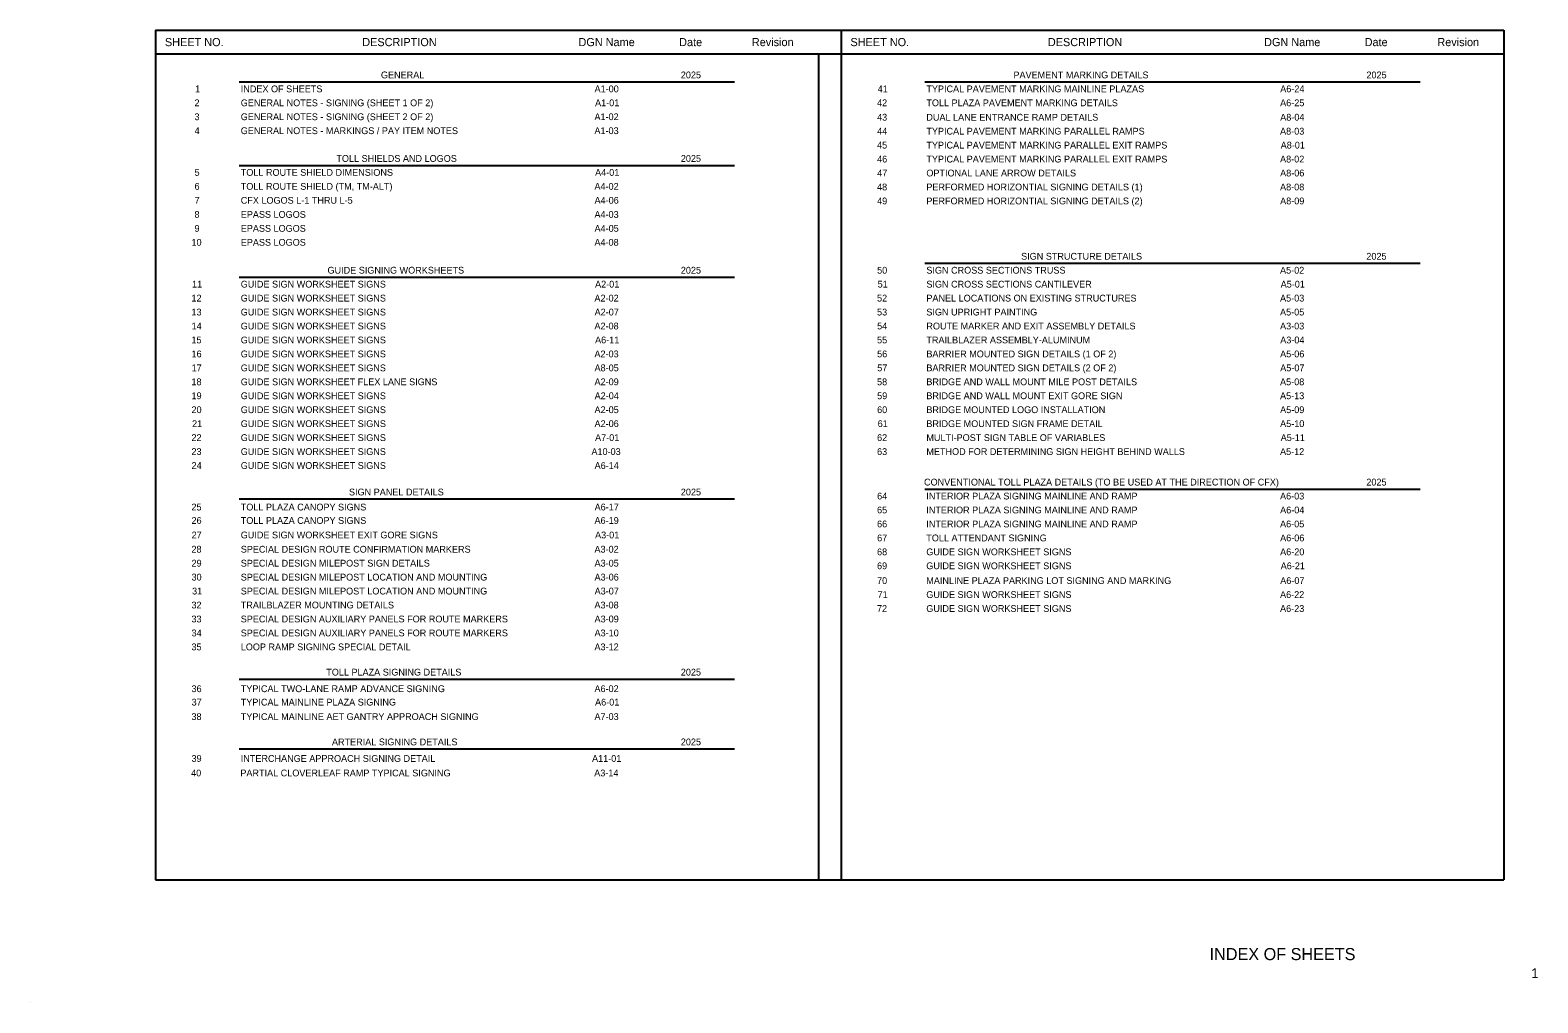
# Model space of a CAD drawing. Extents: x 2479979.8 to 2479999.3, y 3680687.9 to 3680700.4.
import ezdxf

# ---------------------------------------------------------------- set-up
doc = ezdxf.new("R2010")
doc.units = 0
for name, color, linetype in [('AdhocPoint_dp', 7, 'Continuous'), ('SumBoxLines_dp', 7, 'Continuous'), ('TextLabel', 7, 'Continuous'), ('TextMisc', 7, 'Continuous'), ('TextShtNo', 7, 'Continuous')]:
    doc.layers.add(name, color=color, linetype=linetype)

msp = doc.modelspace()

# ---------------------------------------------------------------- linework, layer by layer
at = {"layer": 'AdhocPoint_dp'}
msp.add_line((2479979.842, 3680687.871), (2479979.842, 3680687.871), dxfattribs=at)
at = {"layer": 'SumBoxLines_dp'}
for p, q in [((2479981.458, 3680700.422), (2479998.85, 3680700.422)), ((2479981.458, 3680700.422), (2479981.458, 3680689.458)), ((2479990.3, 3680700.422), (2479990.3, 3680690.034)), ((2479998.85, 3680700.422), (2479998.85, 3680689.458)), ((2479981.458, 3680700.114), (2479998.85, 3680700.114)), ((2479981.458, 3680700.114), (2479998.85, 3680700.114)), ((2479990.008, 3680700.114), (2479990.008, 3680691.294)), ((2479990.008, 3680700.025), (2479990.008, 3680689.458)), ((2479990.3, 3680700.025), (2479990.3, 3680689.458)), ((2479982.538, 3680699.754), (2479988.928, 3680699.754)), ((2479982.538, 3680699.754), (2479988.928, 3680699.754)), ((2479991.381, 3680699.754), (2479997.771, 3680699.754)), ((2479991.381, 3680699.754), (2479997.771, 3680699.754)), ((2479982.538, 3680698.675), (2479988.928, 3680698.675)), ((2479982.538, 3680698.675), (2479988.928, 3680698.675)), ((2479991.381, 3680697.414), (2479997.771, 3680697.414)), ((2479991.381, 3680697.414), (2479997.771, 3680697.414)), ((2479982.538, 3680697.234), (2479988.928, 3680697.234)), ((2479982.538, 3680697.234), (2479988.928, 3680697.234)), ((2479991.38, 3680694.5), (2479997.77, 3680694.5)), ((2479991.38, 3680694.5), (2479997.77, 3680694.5)), ((2479982.538, 3680694.372), (2479988.928, 3680694.372)), ((2479982.538, 3680692.047), (2479988.928, 3680692.047)), ((2479982.538, 3680692.047), (2479988.928, 3680692.047)), ((2479982.538, 3680691.147), (2479988.928, 3680691.147)), ((2479982.538, 3680691.147), (2479988.928, 3680691.147)), ((2479981.458, 3680689.458), (2479998.85, 3680689.458))]:
    msp.add_line(p, q, dxfattribs=at)

# ---------------------------------------------------------------- texts
at = {"layer": 'TextLabel'}
for s, height, p in [('SHEET NO.', 0.105, (2479981.58, 3680700.215)), ('DESCRIPTION', 0.105, (2479984.125, 3680700.215)), ('DGN Name', 0.105, (2479986.914, 3680700.215)), ('Date', 0.105, (2479988.212, 3680700.215)), ('Revision', 0.105, (2479989.15, 3680700.215)), ('SHEET NO.', 0.105, (2479990.422, 3680700.215)), ('DESCRIPTION', 0.105, (2479992.968, 3680700.215)), ('DGN Name', 0.105, (2479995.757, 3680700.215)), ('Date', 0.105, (2479997.054, 3680700.215)), ('Revision', 0.105, (2479997.992, 3680700.215)), ('GENERAL', 0.0875, (2479984.366, 3680699.8)), ('2025', 0.0875, (2479988.234, 3680699.8)), ('PAVEMENT MARKING DETAILS', 0.0875, (2479992.524, 3680699.8)), ('2025', 0.0875, (2479997.077, 3680699.8)), ('2', 0.0875, (2479981.961, 3680699.44)), ('1', 0.0875, (2479981.969, 3680699.62)), ('GENERAL NOTES - SIGNING (SHEET 1 OF 2)', 0.0875, (2479982.558, 3680699.44)), ('INDEX OF SHEETS', 0.0875, (2479982.558, 3680699.62)), ('A1-00', 0.0875, (2479987.121, 3680699.62)), ('A1-01', 0.0875, (2479987.128, 3680699.44)), ('42', 0.0875, (2479990.765, 3680699.44)), ('41', 0.0875, (2479990.773, 3680699.62)), ('TYPICAL PAVEMENT MARKING MAINLINE PLAZAS', 0.0875, (2479991.401, 3680699.62)), ('TOLL PLAZA PAVEMENT MARKING DETAILS', 0.0875, (2479991.401, 3680699.44)), ('A6-25', 0.0875, (2479995.964, 3680699.44)), ('A6-24', 0.0875, (2479995.965, 3680699.62)), ('3', 0.0875, (2479981.961, 3680699.26)), ('GENERAL NOTES - SIGNING (SHEET 2 OF 2)', 0.0875, (2479982.558, 3680699.26)), ('A1-02', 0.0875, (2479987.12, 3680699.26)), ('43', 0.0875, (2479990.765, 3680699.254)), ('DUAL LANE ENTRANCE RAMP DETAILS', 0.0875, (2479991.401, 3680699.254)), ('A8-04', 0.0875, (2479995.965, 3680699.254)), ('4', 0.0875, (2479981.963, 3680699.08)), ('GENERAL NOTES - MARKINGS / PAY ITEM NOTES', 0.0875, (2479982.558, 3680699.08)), ('A1-03', 0.0875, (2479987.12, 3680699.08)), ('44', 0.0875, (2479990.766, 3680699.074)), ('TYPICAL PAVEMENT MARKING PARALLEL RAMPS', 0.0875, (2479991.401, 3680699.074)), ('A8-03', 0.0875, (2479995.963, 3680699.074)), ('45', 0.0875, (2479990.765, 3680698.894)), ('TYPICAL PAVEMENT MARKING PARALLEL EXIT RAMPS', 0.0875, (2479991.401, 3680698.894)), ('A8-01', 0.0875, (2479995.971, 3680698.894)), ('TOLL SHIELDS AND LOGOS', 0.0875, (2479983.791, 3680698.722)), ('2025', 0.0875, (2479988.234, 3680698.722)), ('46', 0.0875, (2479990.766, 3680698.714)), ('TYPICAL PAVEMENT MARKING PARALLEL EXIT RAMPS', 0.0875, (2479991.401, 3680698.714)), ('A8-02', 0.0875, (2479995.963, 3680698.714)), ('5', 0.0875, (2479981.962, 3680698.542)), ('TOLL ROUTE SHIELD DIMENSIONS', 0.0875, (2479982.558, 3680698.542)), ('A4-01', 0.0875, (2479987.128, 3680698.542)), ('47', 0.0875, (2479990.767, 3680698.534)), ('OPTIONAL LANE ARROW DETAILS', 0.0875, (2479991.401, 3680698.534)), ('A8-06', 0.0875, (2479995.964, 3680698.534)), ('6', 0.0875, (2479981.962, 3680698.362)), ('TOLL ROUTE SHIELD (TM, TM-ALT)', 0.0875, (2479982.558, 3680698.362)), ('A4-02', 0.0875, (2479987.12, 3680698.362)), ('48', 0.0875, (2479990.765, 3680698.354)), ('PERFORMED HORIZONTIAL SIGNING DETAILS (1)', 0.0875, (2479991.401, 3680698.354)), ('A8-08', 0.0875, (2479995.963, 3680698.354)), ('7', 0.0875, (2479981.963, 3680698.182)), ('CFX LOGOS L-1 THRU L-5', 0.0875, (2479982.558, 3680698.182)), ('A4-06', 0.0875, (2479987.121, 3680698.182)), ('49', 0.0875, (2479990.766, 3680698.174)), ('PERFORMED HORIZONTIAL SIGNING DETAILS (2)', 0.0875, (2479991.401, 3680698.174)), ('A8-09', 0.0875, (2479995.964, 3680698.174)), ('8', 0.0875, (2479981.961, 3680698)), ('EPASS LOGOS', 0.0875, (2479982.558, 3680698)), ('A4-03', 0.0875, (2479987.12, 3680698)), ('9', 0.0875, (2479981.962, 3680697.82)), ('EPASS LOGOS', 0.0875, (2479982.558, 3680697.82)), ('A4-05', 0.0875, (2479987.121, 3680697.82)), ('10', 0.0875, (2479981.923, 3680697.64)), ('EPASS LOGOS', 0.0875, (2479982.558, 3680697.64)), ('A4-08', 0.0875, (2479987.12, 3680697.64)), ('SIGN STRUCTURE DETAILS', 0.0875, (2479992.623, 3680697.46)), ('2025', 0.0875, (2479997.076, 3680697.46)), ('11', 0.0875, (2479981.93, 3680697.1)), ('GUIDE SIGN WORKSHEET SIGNS', 0.0875, (2479982.558, 3680697.1)), ('GUIDE SIGNING WORKSHEETS', 0.0875, (2479983.677, 3680697.28)), ('A2-01', 0.0875, (2479987.128, 3680697.1)), ('2025', 0.0875, (2479988.234, 3680697.28)), ('50', 0.0875, (2479990.766, 3680697.28)), ('51', 0.0875, (2479990.773, 3680697.1)), ('SIGN CROSS SECTIONS TRUSS', 0.0875, (2479991.401, 3680697.28)), ('SIGN CROSS SECTIONS CANTILEVER', 0.0875, (2479991.401, 3680697.1)), ('A5-02', 0.0875, (2479995.963, 3680697.28)), ('A5-01', 0.0875, (2479995.971, 3680697.1)), ('12', 0.0875, (2479981.922, 3680696.92)), ('GUIDE SIGN WORKSHEET SIGNS', 0.0875, (2479982.558, 3680696.92)), ('A2-02', 0.0875, (2479987.12, 3680696.92)), ('52', 0.0875, (2479990.765, 3680696.92)), ('PANEL LOCATIONS ON EXISTING STRUCTURES', 0.0875, (2479991.401, 3680696.92)), ('A5-03', 0.0875, (2479995.963, 3680696.92)), ('13', 0.0875, (2479981.922, 3680696.74)), ('GUIDE SIGN WORKSHEET SIGNS', 0.0875, (2479982.558, 3680696.74)), ('A2-07', 0.0875, (2479987.122, 3680696.74)), ('53', 0.0875, (2479990.765, 3680696.74)), ('SIGN UPRIGHT PAINTING', 0.0875, (2479991.401, 3680696.74)), ('A5-05', 0.0875, (2479995.963, 3680696.74)), ('14', 0.0875, (2479981.924, 3680696.56)), ('GUIDE SIGN WORKSHEET SIGNS', 0.0875, (2479982.558, 3680696.56)), ('A2-08', 0.0875, (2479987.12, 3680696.56)), ('54', 0.0875, (2479990.766, 3680696.56)), ('ROUTE MARKER AND EXIT ASSEMBLY DETAILS', 0.0875, (2479991.401, 3680696.56)), ('A3-03', 0.0875, (2479995.963, 3680696.56)), ('15', 0.0875, (2479981.922, 3680696.38)), ('GUIDE SIGN WORKSHEET SIGNS', 0.0875, (2479982.558, 3680696.38)), ('A6-11', 0.0875, (2479987.128, 3680696.38)), ('55', 0.0875, (2479990.765, 3680696.38)), ('TRAILBLAZER ASSEMBLY-ALUMINUM', 0.0875, (2479991.401, 3680696.38)), ('A3-04', 0.0875, (2479995.965, 3680696.38)), ('16', 0.0875, (2479981.923, 3680696.2)), ('GUIDE SIGN WORKSHEET SIGNS', 0.0875, (2479982.558, 3680696.2)), ('A2-03', 0.0875, (2479987.12, 3680696.2)), ('56', 0.0875, (2479990.766, 3680696.2)), ('BARRIER MOUNTED SIGN DETAILS (1 OF 2)', 0.0875, (2479991.401, 3680696.2)), ('A5-06', 0.0875, (2479995.964, 3680696.2)), ('17', 0.0875, (2479981.924, 3680696.02)), ('GUIDE SIGN WORKSHEET SIGNS', 0.0875, (2479982.558, 3680696.02)), ('A8-05', 0.0875, (2479987.121, 3680696.02)), ('57', 0.0875, (2479990.767, 3680696.02)), ('BARRIER MOUNTED SIGN DETAILS (2 OF 2)', 0.0875, (2479991.401, 3680696.02)), ('A5-07', 0.0875, (2479995.965, 3680696.02)), ('18', 0.0875, (2479981.922, 3680695.84)), ('GUIDE SIGN WORKSHEET FLEX LANE SIGNS', 0.0875, (2479982.558, 3680695.84)), ('A2-09', 0.0875, (2479987.121, 3680695.84)), ('58', 0.0875, (2479990.765, 3680695.84)), ('BRIDGE AND WALL MOUNT MILE POST DETAILS', 0.0875, (2479991.401, 3680695.84)), ('A5-08', 0.0875, (2479995.963, 3680695.84)), ('19', 0.0875, (2479981.923, 3680695.66)), ('GUIDE SIGN WORKSHEET SIGNS', 0.0875, (2479982.558, 3680695.66)), ('A2-04', 0.0875, (2479987.122, 3680695.66)), ('59', 0.0875, (2479990.766, 3680695.66)), ('BRIDGE AND WALL MOUNT EXIT GORE SIGN', 0.0875, (2479991.401, 3680695.66)), ('A5-13', 0.0875, (2479995.963, 3680695.66)), ('20', 0.0875, (2479981.923, 3680695.48)), ('GUIDE SIGN WORKSHEET SIGNS', 0.0875, (2479982.558, 3680695.48)), ('A2-05', 0.0875, (2479987.121, 3680695.48)), ('60', 0.0875, (2479990.766, 3680695.48)), ('BRIDGE MOUNTED LOGO INSTALLATION', 0.0875, (2479991.401, 3680695.48)), ('A5-09', 0.0875, (2479995.964, 3680695.48)), ('21', 0.0875, (2479981.93, 3680695.3)), ('GUIDE SIGN WORKSHEET SIGNS', 0.0875, (2479982.558, 3680695.3)), ('A2-06', 0.0875, (2479987.121, 3680695.3)), ('61', 0.0875, (2479990.773, 3680695.3)), ('BRIDGE MOUNTED SIGN FRAME DETAIL', 0.0875, (2479991.401, 3680695.3)), ('A5-10', 0.0875, (2479995.964, 3680695.3)), ('22', 0.0875, (2479981.922, 3680695.12)), ('GUIDE SIGN WORKSHEET SIGNS', 0.0875, (2479982.558, 3680695.12)), ('A7-01', 0.0875, (2479987.128, 3680695.12)), ('62', 0.0875, (2479990.765, 3680695.12)), ('MULTI-POST SIGN TABLE OF VARIABLES', 0.0875, (2479991.401, 3680695.12)), ('A5-11', 0.0875, (2479995.971, 3680695.12)), ('23', 0.0875, (2479981.922, 3680694.94)), ('GUIDE SIGN WORKSHEET SIGNS', 0.0875, (2479982.558, 3680694.94)), ('A10-03', 0.0875, (2479987.081, 3680694.94)), ('63', 0.0875, (2479990.765, 3680694.94)), ('METHOD FOR DETERMINING SIGN HEIGHT BEHIND WALLS', 0.0875, (2479991.401, 3680694.94)), ('A5-12', 0.0875, (2479995.963, 3680694.94)), ('24', 0.0875, (2479981.924, 3680694.76)), ('GUIDE SIGN WORKSHEET SIGNS', 0.0875, (2479982.558, 3680694.76)), ('A6-14', 0.0875, (2479987.122, 3680694.76)), ('SIGN PANEL DETAILS', 0.0875, (2479983.954, 3680694.418)), ('2025', 0.0875, (2479988.234, 3680694.418)), ('CONVENTIONAL TOLL PLAZA DETAILS (TO BE USED AT THE DIRECTION OF CFX)', 0.0875, (2479991.371, 3680694.546)), ('2025', 0.0875, (2479997.076, 3680694.546)), ('25', 0.0875, (2479981.922, 3680694.224)), ('TOLL PLAZA CANOPY SIGNS', 0.0875, (2479982.558, 3680694.224)), ('A6-17', 0.0875, (2479987.122, 3680694.224)), ('65', 0.0875, (2479990.765, 3680694.186)), ('64', 0.0875, (2479990.766, 3680694.366)), ('INTERIOR PLAZA SIGNING MAINLINE AND RAMP', 0.0875, (2479991.4, 3680694.366)), ('INTERIOR PLAZA SIGNING MAINLINE AND RAMP', 0.0875, (2479991.4, 3680694.186)), ('A6-03', 0.0875, (2479995.963, 3680694.366)), ('A6-04', 0.0875, (2479995.964, 3680694.186)), ('26', 0.0875, (2479981.923, 3680694.051)), ('TOLL PLAZA CANOPY SIGNS', 0.0875, (2479982.558, 3680694.051)), ('A6-19', 0.0875, (2479987.121, 3680694.051)), ('66', 0.0875, (2479990.765, 3680694.006)), ('INTERIOR PLAZA SIGNING MAINLINE AND RAMP', 0.0875, (2479991.4, 3680694.006)), ('A6-05', 0.0875, (2479995.963, 3680694.006)), ('27', 0.0875, (2479981.924, 3680693.864)), ('GUIDE SIGN WORKSHEET EXIT GORE SIGNS', 0.0875, (2479982.558, 3680693.864)), ('A3-01', 0.0875, (2479987.128, 3680693.864)), ('67', 0.0875, (2479990.766, 3680693.826)), ('TOLL ATTENDANT SIGNING', 0.0875, (2479991.4, 3680693.826)), ('A6-06', 0.0875, (2479995.964, 3680693.826)), ('28', 0.0875, (2479981.922, 3680693.68)), ('SPECIAL DESIGN ROUTE CONFIRMATION MARKERS', 0.0875, (2479982.558, 3680693.68)), ('A3-02', 0.0875, (2479987.12, 3680693.68)), ('68', 0.0875, (2479990.765, 3680693.646)), ('GUIDE SIGN WORKSHEET SIGNS ', 0.0875, (2479991.4, 3680693.646)), ('A6-20', 0.0875, (2479995.964, 3680693.646)), ('29', 0.0875, (2479981.923, 3680693.5)), ('SPECIAL DESIGN MILEPOST SIGN DETAILS', 0.0875, (2479982.558, 3680693.5)), ('A3-05', 0.0875, (2479987.121, 3680693.5)), ('69', 0.0875, (2479990.765, 3680693.466)), ('GUIDE SIGN WORKSHEET SIGNS ', 0.0875, (2479991.4, 3680693.466)), ('A6-21', 0.0875, (2479995.971, 3680693.466)), ('30', 0.0875, (2479981.923, 3680693.32)), ('SPECIAL DESIGN MILEPOST LOCATION AND MOUNTING', 0.0875, (2479982.558, 3680693.32)), ('A3-06', 0.0875, (2479987.121, 3680693.32)), ('70', 0.0875, (2479990.765, 3680693.275)), ('MAINLINE PLAZA PARKING LOT SIGNING AND MARKING', 0.0875, (2479991.4, 3680693.275)), ('A6-07', 0.0875, (2479995.965, 3680693.275)), ('31', 0.0875, (2479981.93, 3680693.14)), ('SPECIAL DESIGN MILEPOST LOCATION AND MOUNTING', 0.0875, (2479982.558, 3680693.14)), ('A3-07', 0.0875, (2479987.122, 3680693.14)), ('71', 0.0875, (2479990.772, 3680693.095)), ('GUIDE SIGN WORKSHEET SIGNS', 0.0875, (2479991.4, 3680693.095)), ('A6-22', 0.0875, (2479995.963, 3680693.095)), ('32', 0.0875, (2479981.922, 3680692.96)), ('TRAILBLAZER MOUNTING DETAILS', 0.0875, (2479982.558, 3680692.96)), ('A3-08', 0.0875, (2479987.12, 3680692.96)), ('72', 0.0875, (2479990.764, 3680692.915)), ('GUIDE SIGN WORKSHEET SIGNS', 0.0875, (2479991.4, 3680692.915)), ('A6-23', 0.0875, (2479995.963, 3680692.915)), ('33', 0.0875, (2479981.922, 3680692.78)), ('SPECIAL DESIGN AUXILIARY PANELS FOR ROUTE MARKERS', 0.0875, (2479982.558, 3680692.78)), ('A3-09', 0.0875, (2479987.121, 3680692.78)), ('34', 0.0875, (2479981.924, 3680692.6)), ('SPECIAL DESIGN AUXILIARY PANELS FOR ROUTE MARKERS', 0.0875, (2479982.558, 3680692.6)), ('A3-10', 0.0875, (2479987.121, 3680692.6)), ('35', 0.0875, (2479981.922, 3680692.42)), ('LOOP RAMP SIGNING SPECIAL DETAIL', 0.0875, (2479982.558, 3680692.42)), ('A3-12', 0.0875, (2479987.12, 3680692.42)), ('TOLL PLAZA SIGNING DETAILS', 0.0875, (2479983.661, 3680692.094)), ('2025', 0.0875, (2479988.234, 3680692.094)), ('36', 0.0875, (2479981.923, 3680691.88)), ('TYPICAL TWO-LANE RAMP ADVANCE SIGNING', 0.0875, (2479982.558, 3680691.88)), ('A6-02', 0.0875, (2479987.12, 3680691.88)), ('37', 0.0875, (2479981.924, 3680691.707)), ('TYPICAL MAINLINE PLAZA SIGNING', 0.0875, (2479982.558, 3680691.707)), ('A6-01', 0.0875, (2479987.128, 3680691.707)), ('38', 0.0875, (2479981.922, 3680691.52)), ('TYPICAL MAINLINE AET GANTRY APPROACH SIGNING', 0.0875, (2479982.558, 3680691.52)), ('A7-03', 0.0875, (2479987.12, 3680691.52)), ('ARTERIAL SIGNING DETAILS', 0.0875, (2479983.734, 3680691.194)), ('2025', 0.0875, (2479988.234, 3680691.194)), ('39', 0.0875, (2479981.923, 3680690.98)), ('INTERCHANGE APPROACH SIGNING DETAIL', 0.0875, (2479982.558, 3680690.98)), ('A11-01', 0.0875, (2479987.089, 3680690.98)), ('40', 0.0875, (2479981.918, 3680690.793)), ('PARTIAL CLOVERLEAF RAMP TYPICAL SIGNING', 0.0875, (2479982.553, 3680690.793)), ('A3-14', 0.0875, (2479987.117, 3680690.793))]:
    msp.add_text(s, height=height, dxfattribs=at).set_placement(p)
at = {"layer": 'TextMisc'}
msp.add_text('       INDEX OF SHEETS         ', height=0.15625, rotation=360, dxfattribs=at).set_placement((2479994.648, 3680688.422))
at = {"layer": 'TextShtNo'}
msp.add_text('  1  ', height=0.125, rotation=360, dxfattribs=at).set_placement((2479999.11, 3680688.19))

doc.saveas('drawing.dxf')
